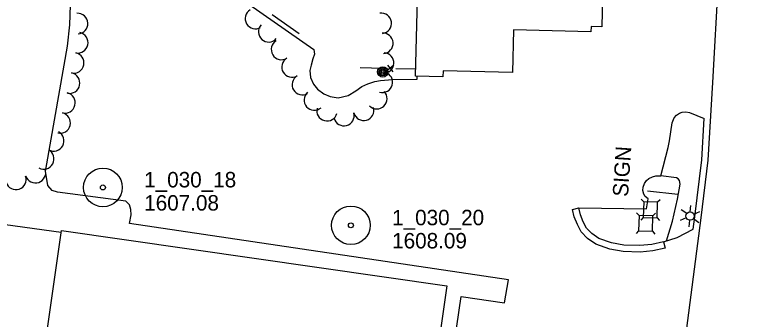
# Model space of a CAD drawing. Extents: x 189384 to 193282, y 256970 to 260388.
# Drawn here: x 190703.8 to 190986.9, y 259516.4 to 259634.9 of the extents above; entities that cross this region are included whole.
import ezdxf

# ---------------------------------------------------------------- set-up
doc = ezdxf.new("R2010")
doc.units = 0
for name, color, linetype in [('E_DWY', 7, 'Continuous'), ('E_LAND_Vegetation', 7, 'Continuous'), ('E_MAP_PassPoints', 7, 'Continuous'), ('E_MISCPROP', 7, 'Continuous'), ('E_MISCPROP_HvyLine', 7, 'Continuous'), ('E_MISCPROP_Railing', 7, 'Continuous'), ('E_PATH_Sidewalk', 7, 'Continuous'), ('E_RDWY', 7, 'Continuous'), ('E_UTL_AboveGroundPipe', 7, 'Continuous')]:
    doc.layers.add(name, color=color, linetype=linetype)

# ---------------------------------------------------------------- blocks, each defined once
blk = doc.blocks.new('PP')
at = {"layer": 'E_MAP_PassPoints'}
for radius in [7.5, 0.96]:
    blk.add_circle((0, 0), radius, dxfattribs=at)
blk = doc.blocks.new('PED')
at = {"layer": 'E_UTL_AboveGroundPipe'}
for p, q in [((-2.34, 2.71), (-3.29, 3.77)), ((3.06, 2.71), (4.02, 3.77)), ((-3.29, -4.35), (-2.34, -3.29)), ((4.02, -4.35), (3.06, -3.29))]:
    blk.add_line(p, q, dxfattribs=at)
blk.add_lwpolyline([(-2.34, -3.29), (3.06, -3.29), (3.06, 2.71), (-2.34, 2.71)], close=True, dxfattribs=at)
blk = doc.blocks.new('LTP_1')
at = {"layer": 'E_MISCPROP'}
for p, q in [((-0.78, 1.46), (-1.98, 3.76)), ((0.86, 1.37), (2.22, 3.6)), ((-1.61, 0.09), (-4.22, 0.17)), ((1.66, 0), (4.18, -0.07)), ((-0.86, -1.4), (-2.22, -3.59)), ((0.78, -1.44), (2.02, -3.62))]:
    blk.add_line(p, q, dxfattribs=at)
blk.add_circle((0.02, 0.01), 1.64, dxfattribs=at)
blk = doc.blocks.new('POLE_1')
at = {"layer": 'E_MISCPROP'}
for radius in [2.02, 1.51, 1.01, 0.504]:
    blk.add_circle((0.03, -0.09), radius, dxfattribs=at)
blk = doc.blocks.new('SIGN_4')
at = {"layer": 'E_MISCPROP'}
blk.add_text('SIGN', height=6, rotation=0, dxfattribs=at).set_placement((-9.6, -3.01))

msp = doc.modelspace()

# ---------------------------------------------------------------- linework, layer by layer
at = {"layer": 'E_DWY'}
for points in [[(190748.43, 259553.64), (190748.99, 259557.07), (190748.96, 259559.1), (190748.37, 259560.95), (190747.01, 259562.36), (190720.5, 259565.8), (190718.33, 259566.57), (190716.64, 259568.39), (190715.81, 259574), (190716.36, 259576.89), (190724.3, 259622.64), (190725.28, 259630.81), (190726.64, 259673.45)], [(190789.08, 259642.89), (190819.96, 259621.32), (190820.18, 259619.52), (190819.54, 259617.71), (190818.8, 259615.25), (190818.32, 259613.1), (190818.62, 259610.43), (190819.71, 259607.83), (190821.26, 259605.92), (190823.75, 259604.02), (190826.17, 259602.98), (190829.35, 259602.45), (190833.27, 259603.44), (190836.25, 259605.22), (190838.51, 259606.86), (190840.82, 259608.01), (190843.52, 259608.82), (190845.81, 259609.23), (190850.37, 259609.61), (190860.05, 259609.7), (190860.04, 259610.85)], [(190957.82, 259585.85), (190958.96, 259592.85), (190959.67, 259594.71), (190960.63, 259595.79), (190961.7, 259596.58), (190962.8, 259596.98), (190964.28, 259597.1), (190965.66, 259596.78), (190971.37, 259594.53)], [(190922.72, 259559.73), (190948.95, 259559.38), (190949.54, 259563.28), (190948.41, 259564.15), (190947.94, 259565.11), (190947.56, 259566.48), (190947.71, 259567.84), (190948.16, 259569.19), (190948.93, 259570.39), (190949.92, 259571.18), (190951.31, 259571.82), (190952.59, 259572.15), (190954.47, 259572.17), (190957.34, 259583.16), (190957.82, 259585.85)], [(190955.6, 259546.6), (190956.15, 259544.16), (190951.46, 259543.09), (190946.46, 259542.57), (190939.89, 259542.8), (190934.72, 259543.73), (190929.35, 259545.6), (190926.08, 259547.89), (190923.64, 259550.43), (190922.17, 259553.28), (190920.95, 259556.32), (190920.29, 259559.16), (190922.72, 259559.73)], [(190955.6, 259546.6), (190951.05, 259545.56), (190946.37, 259545.08), (190940.15, 259545.3), (190935.36, 259546.16), (190930.5, 259547.85), (190927.71, 259549.8), (190925.7, 259551.9), (190924.45, 259554.33), (190923.34, 259557.07), (190922.72, 259559.73)], [(190670.76, 259448.61), (190677.52, 259447.58), (190692.62, 259554.31), (190721.93, 259550.33)], [(190746.64, 259479.9), (190743.07, 259458.2), (190751.43, 259457.02), (190754.21, 259474.4), (190867.37, 259458.79), (190877.01, 259525.35), (190893.9, 259522.85), (190895.42, 259531.86), (190748.43, 259553.64)], [(190955.6, 259546.6), (190960.81, 259548.28), (190967.05, 259551.5)]]:
    msp.add_lwpolyline(points, dxfattribs=at)
at = {"layer": 'E_LAND_Vegetation'}
for centre, radius, start, end in [((190797.24, 259633.29), 3.97, 120.5768, 300.5615), ((190728.21, 259631.36), 4, 273.0708, 93.0555), ((190846.04, 259631.48), 3.97, 277.5598, 97.5445), ((190802.37, 259628.16), 3.97, 137.9868, 317.9715), ((190728.31, 259623.92), 4, 258.5397, 78.5244), ((190846.68, 259623.69), 3.97, 274.2336, 94.2183), ((190807.37, 259621.3), 3.97, 120.8622, 300.8468), ((190726.72, 259616.08), 4, 258.5397, 78.5244), ((190847, 259616.03), 3.97, 266.8186, 86.8033), ((190811.44, 259614.45), 3.97, 120.2103, 300.195), ((190725.13, 259608.24), 4, 258.5397, 78.5244), ((190815.44, 259607.58), 3.97, 120.2103, 300.195), ((190846.52, 259608.58), 3.97, 253.7935, 73.7782), ((190844.34, 259602.16), 3.97, 224.3922, 44.3769), ((190723.33, 259600.52), 4, 256.6555, 76.6401), ((190820.07, 259601.66), 3.97, 131.16, 311.1446), ((190721.48, 259592.74), 4, 256.6555, 76.6401), ((190825.01, 259597.5), 3.97, 164.979, 344.9637), ((190831.59, 259595.59), 3.97, 195.2124, 15.1971), ((190839.26, 259597.67), 3.97, 195.2124, 15.1971), ((190718.95, 259585.81), 4, 241.3792, 61.3639), ((190715.11, 259578.79), 4, 241.3792, 61.3639), ((190711.88, 259573.42), 4, 198.8685, 18.8531), ((190704.31, 259570.83), 4, 198.8685, 18.8531)]:
    msp.add_arc(centre, radius, start, end, dxfattribs=at)
at = {"layer": 'E_MISCPROP'}
msp.add_line((190949.37, 259566.44), (190961.16, 259565.1), dxfattribs=at)
at = {"layer": 'E_MISCPROP_HvyLine'}
for points in [[(190859.39, 259610.87), (190861.22, 259685.89), (190861.22, 259685.89), (190903.71, 259684.86), (190903.71, 259684.86), (190903.71, 259684.86), (190903.8, 259688.61), (190903.8, 259688.61), (190932.97, 259687.9), (190931.57, 259630.12), (190931.57, 259630.12), (190931.57, 259630.12), (190927.46, 259630.22), (190927.46, 259630.22), (190927.41, 259628.17), (190897.31, 259628.91), (190897.31, 259628.91), (190897.31, 259628.91), (190896.91, 259612.39), (190896.91, 259612.39), (190870.06, 259613.04), (190870.06, 259613.04), (190870, 259610.61), (190870, 259610.61)], [(190862.07, 259463.38), (190862.07, 259463.38), (190712.55, 259484.77), (190712.55, 259484.77), (190722.01, 259550.92), (190871.53, 259529.52), (190871.53, 259529.52), (190871.53, 259529.52)]]:
    msp.add_lwpolyline(points, close=True, dxfattribs=at)
at = {"layer": 'E_MISCPROP_Railing'}
for p, q in [((190850.9, 259615.14), (190847.97, 259612.71)), ((190850.71, 259612.64), (190848.61, 259615.14))]:
    msp.add_line(p, q, dxfattribs=at)
for points in [[(190803.78, 259634.83), (190814.25, 259627.45)], [(190846.68, 259613.9), (190837.93, 259614.11)], [(190859.46, 259613.59), (190851.76, 259613.78)]]:
    msp.add_lwpolyline(points, dxfattribs=at)
at = {"layer": 'E_PATH_Sidewalk'}
msp.add_lwpolyline([(190956.68, 259546.95), (190959.1, 259554.62), (190960.97, 259563.08), (190962, 259568.98), (190961.71, 259570.35), (190961.21, 259571.05), (190960.53, 259571.39), (190954.47, 259572.17)], dxfattribs=at)
at = {"layer": 'E_RDWY'}
for points in [[(190963.74, 259505.98), (190970.14, 259555.94), (190972.91, 259578.23), (190974.7, 259608.44), (190976.95, 259647.97), (190979.82, 259699.42), (190982.53, 259748.59), (190986.45, 259813.95), (190986.94, 259824.97), (190986.74, 259828.53), (190985.6, 259832.73), (190983.96, 259836.38), (190981.1, 259840.4), (190979.3, 259842.62), (190977.35, 259841.05)], [(190963.74, 259505.98), (190970.14, 259555.94), (190972.91, 259578.23), (190974.7, 259608.44), (190976.95, 259647.97), (190979.82, 259699.42), (190982.53, 259748.59), (190986.45, 259813.95), (190986.94, 259824.97), (190986.74, 259828.53), (190985.6, 259832.73), (190983.96, 259836.38), (190981.1, 259840.4), (190979.3, 259842.62), (190977.35, 259841.05)], [(190967.05, 259551.5), (190967.66, 259556.25), (190970.42, 259578.46), (190971.37, 259594.53)]]:
    msp.add_lwpolyline(points, dxfattribs=at)

# ---------------------------------------------------------------- block references
at = {"layer": 'E_MAP_PassPoints'}
for p, rotation in [((190738.08, 259567.69), 0.04071554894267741), ((190834.27, 259552.98), 0.04071383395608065)]:
    msp.add_blockref('PP', p, dxfattribs=dict(at, rotation=rotation))
at = {"layer": 'E_MISCPROP', "xscale": 1.000001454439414}
for name, p, yscale, rotation in [('POLE_1', (190846.53, 259612.57), 1.0000014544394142, 86.27232100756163), ('LTP_1', (190965.85, 259556.57), 1.000001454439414, 86.2723188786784)]:
    msp.add_blockref(name, p, dxfattribs=dict(at, yscale=yscale, rotation=rotation))
at = {"layer": 'E_MISCPROP', "rotation": 86.19316517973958}
msp.add_blockref('SIGN_4', (190939.41, 259573.7), dxfattribs=at)
at = {"layer": 'E_UTL_AboveGroundPipe'}
for p, xscale, yscale, rotation in [((190950.85, 259558.68), 0.999997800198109, 0.9999978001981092, 178.52107738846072), ((190949.03, 259553.43), 0.9999978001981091, 0.9999978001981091, 178.52107742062)]:
    msp.add_blockref('PED', p, dxfattribs=dict(at, xscale=xscale, yscale=yscale, rotation=rotation))

# ---------------------------------------------------------------- texts
at = {"layer": 'E_MAP_PassPoints'}
for s, p in [('1_030_18', (190754.08, 259567.7)), ('1607.08', (190754.09, 259558.7)), ('1_030_20', (190850.27, 259552.99)), ('1608.09', (190850.28, 259543.99))]:
    msp.add_text(s, height=6, rotation=0.0407, dxfattribs=at).set_placement(p)

doc.saveas('drawing.dxf')
